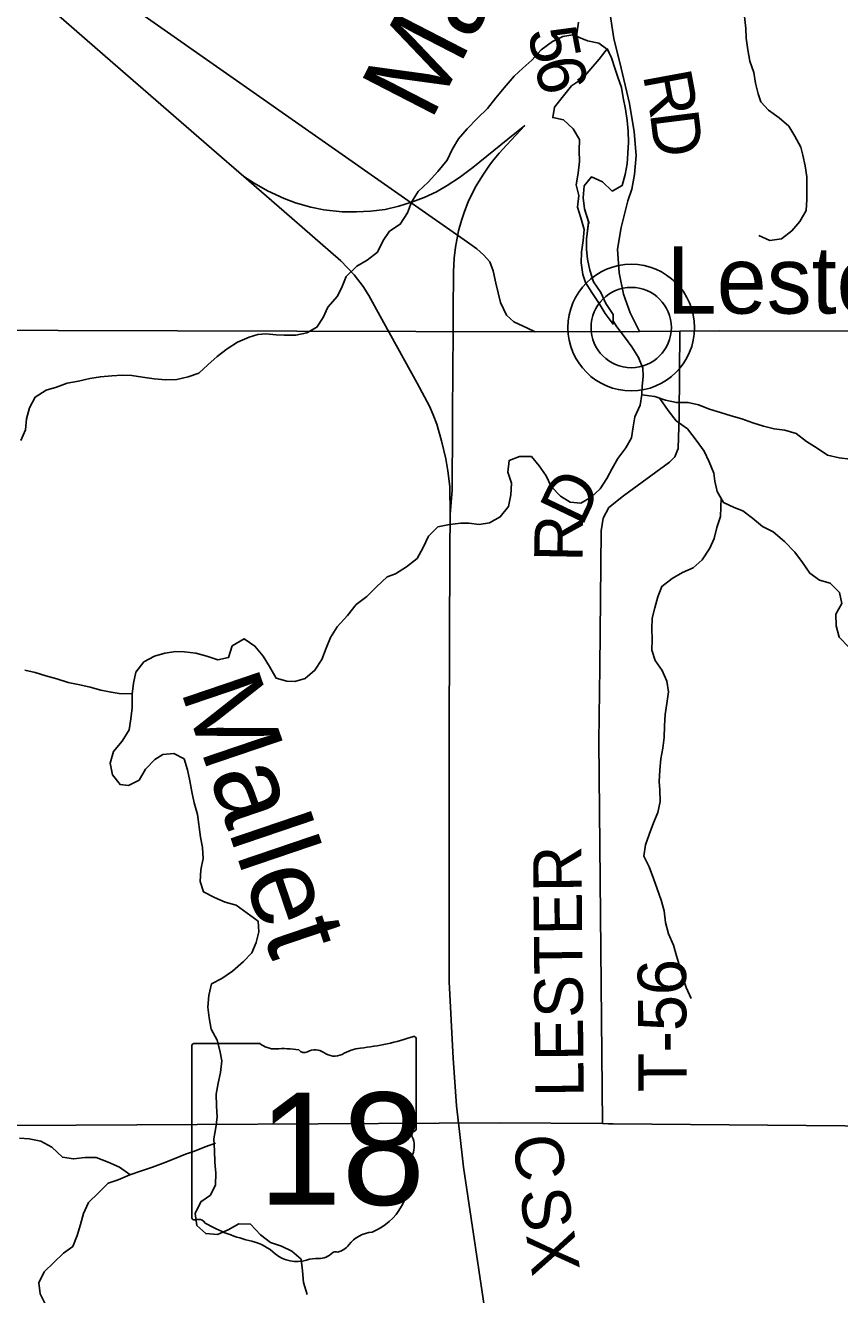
# Model space of a CAD drawing. Extents: x 1985906 to 2277390, y 930619 to 1324581.
# Drawn here: x 2119498 to 2124548, y 1153220 to 1161092 of the extents above; entities that cross this region are included whole.
import ezdxf

# ---------------------------------------------------------------- set-up
doc = ezdxf.new("R2010")
doc.units = 0
for name, color, linetype in [('GM_X_County_Road', 7, 'Continuous'), ('GM_X_County_Road_Text', 7, 'Continuous'), ('GM_X_Minor_Lake', 7, 'Continuous'), ('GM_X_Minor_River', 7, 'Continuous'), ('GM_X_Minor_River_Text', 7, 'Continuous'), ('GM_X_Rail_Line', 7, 'Continuous'), ('GM_X_Rail_Line_Text', 7, 'Continuous'), ('GM_X_State_Location', 7, 'Continuous'), ('GM_X_State_Route', 7, 'Continuous'), ('GM_X_State_Shield', 7, 'Continuous'), ('GM_X_Township_Road', 7, 'Continuous'), ('GM_X_Township_Road_Text', 7, 'Continuous'), ('GM_X_Unincorporated', 7, 'Continuous'), ('GM_X_Unincorporated_Location', 7, 'Continuous'), ('GM_X_Unincorporated_Text', 7, 'Continuous')]:
    doc.layers.add(name, color=color, linetype=linetype)

msp = doc.modelspace()

# ---------------------------------------------------------------- linework, layer by layer
at = {"layer": 'GM_X_County_Road'}
msp.add_lwpolyline([(2123307.7, 1159193.1), (2123249, 1159309.1), (2123208.2, 1159425.2), (2123181.4, 1159557.5), (2123170.4, 1159703.9), (2123193.6, 1159838.4), (2123234.5, 1160003.1), (2123260.1, 1160075.5), (2123275.5, 1160167.9), (2123286.7, 1160284.3), (2123273.8, 1160430.7), (2123244.7, 1160607), (2123193.3, 1160825.4), (2123148.1, 1161009.7), (2123121, 1161186.1)], dxfattribs=at)
at = {"layer": 'GM_X_Minor_Lake'}
for points in [[(2123106.6, 1160946.8), (2123057.6, 1160882), (2122952.7, 1160762.1), (2122886.3, 1160716.2), (2122835.8, 1160654.3), (2122779.3, 1160584.3), (2122769, 1160520.1), (2122835.1, 1160505.6), (2122895, 1160451.1), (2122934.8, 1160384.6), (2122932.5, 1160316.3), (2122934.1, 1160248), (2122927.7, 1160175.8), (2122913.4, 1160103.5), (2122931.1, 1160037.2), (2122922.7, 1159964.9), (2122942.4, 1159898.5), (2122964.1, 1159826.1), (2122957.8, 1159757.9), (2122947.4, 1159685.6), (2122945.1, 1159619.3), (2122954.7, 1159547), (2122972.5, 1159496.7), (2123012.3, 1159434.2), (2123056.1, 1159367.7), (2123093.9, 1159305.2), (2123143.7, 1159238.7), (2123144, 1159298.9), (2123098.3, 1159367.5), (2123066.5, 1159435.9), (2123022.7, 1159500.4), (2122999, 1159572.9), (2122985.3, 1159641.2), (2122977.6, 1159701.5), (2122977.9, 1159765.8), (2122990.8, 1159873.9)], [(2123106, 1160946), (2123057.6, 1160882), (2122952.7, 1160762.1), (2122886.3, 1160716.2), (2122835.8, 1160654.3), (2122779.3, 1160584.3), (2122769, 1160520.1), (2122835.1, 1160505.6), (2122895, 1160451.1), (2122934.8, 1160384.6), (2122932.5, 1160316.3), (2122934.1, 1160248), (2122927.7, 1160175.8), (2122913.4, 1160103.5), (2122931.1, 1160037.2), (2122922.7, 1159964.9), (2122942.4, 1159898.5), (2122964.1, 1159826.1), (2122957.8, 1159757.9), (2122947.4, 1159685.6), (2122945.1, 1159619.3), (2122954.7, 1159547), (2122972.5, 1159496.7), (2123012.3, 1159434.2), (2123056.1, 1159367.7), (2123093.9, 1159305.2), (2123143.7, 1159238.7), (2123144, 1159298.9), (2123098.3, 1159367.5), (2123066.5, 1159435.9), (2123022.7, 1159500.4), (2122999, 1159572.9), (2122985.3, 1159641.2), (2122977.6, 1159701.5), (2122977.9, 1159765.8), (2122990, 1159866.9)], [(2122994.1, 1159862.7), (2122966.8, 1159954.6), (2122957.1, 1160023), (2122963.5, 1160097.2), (2123009.9, 1160153.2), (2123077.9, 1160120.7), (2123137.8, 1160064.1), (2123200.1, 1160097.9), (2123218.5, 1160166.1), (2123230.9, 1160232.3), (2123235.2, 1160298.6), (2123239.5, 1160366.8), (2123235.9, 1160435.1), (2123230.2, 1160501.5), (2123220.5, 1160571.8), (2123204.8, 1160642.2), (2123195.1, 1160706.5), (2123173.4, 1160770.9), (2123155.5, 1160821.2), (2123133.8, 1160889.6), (2123106, 1160948)], [(2122990.8, 1159873.9), (2122966.8, 1159954.6), (2122957.1, 1160023), (2122963.5, 1160097.2), (2123009.9, 1160153.2), (2123077.9, 1160120.7), (2123137.8, 1160064.1), (2123200.1, 1160097.9), (2123218.5, 1160166.1), (2123230.9, 1160232.3), (2123235.2, 1160298.6), (2123239.5, 1160366.8), (2123235.9, 1160435.1), (2123230.2, 1160501.5), (2123220.5, 1160571.8), (2123204.8, 1160642.2), (2123195.1, 1160706.5), (2123173.4, 1160770.9), (2123155.5, 1160821.2), (2123133.8, 1160889.6), (2123106.6, 1160946.8)]]:
    msp.add_lwpolyline(points, dxfattribs=at)
at = {"layer": 'GM_X_Minor_River'}
for points in [[(2122916.9, 1161025.4), (2122928.3, 1161111.6)], [(2124046.9, 1159788), (2124115, 1159757.5), (2124187.2, 1159767.2), (2124251.7, 1159817), (2124302.1, 1159875), (2124340.5, 1159943.1), (2124344.9, 1160011.3), (2124345.6, 1160151.9), (2124333.9, 1160220.2), (2124320.2, 1160286.6), (2124308.4, 1160336.9), (2124270.6, 1160405.4), (2124232.8, 1160465.8), (2124172.9, 1160518.4), (2124106.9, 1160566.9), (2124059.1, 1160617.4), (2124043.3, 1160667.7), (2124027.5, 1160734.1), (2124015.8, 1160800.4), (2123992.1, 1160870.8), (2123978.4, 1160939.2), (2123968.7, 1161011.5), (2123967, 1161071.8), (2123957.4, 1161146.2)], [(2119470, 1158517.9), (2119498.4, 1158584), (2119504.8, 1158652.2), (2119523.2, 1158720.4), (2119559.6, 1158786.5), (2119628, 1158830.3), (2119692.3, 1158848), (2119756.6, 1158871.8), (2119828.8, 1158885.4), (2119899.1, 1158901.1), (2119963.3, 1158912.8), (2120033.6, 1158918.4), (2120097.7, 1158922.1), (2120157.9, 1158919.8), (2120224, 1158909.3), (2120296.2, 1158898.9), (2120370.4, 1158892.5), (2120438.6, 1158896.1), (2120508.8, 1158911.8), (2120573.1, 1158935.5), (2120629.5, 1158987.4), (2120687.9, 1159037.3), (2120750.4, 1159085.2), (2120814.7, 1159127), (2120887.1, 1159158.7), (2120939.3, 1159174.5), (2120989.5, 1159178.2), (2121053.6, 1159171.9), (2121103.8, 1159169.6), (2121176, 1159171.2), (2121244.2, 1159184.9), (2121306.6, 1159220.7), (2121345, 1159280.7), (2121373.4, 1159344.8), (2121433.9, 1159412.8), (2121462.2, 1159472.9), (2121488.6, 1159535), (2121553.1, 1159598.9), (2121617.5, 1159634.7), (2121681.9, 1159684.6), (2121718.3, 1159756.7), (2121756.7, 1159814.7), (2121823.1, 1159858.5), (2121867.6, 1159928.6), (2121894, 1159994.7), (2121934.4, 1160060.7), (2121996.9, 1160118.6), (2122055.4, 1160184.6), (2122113.9, 1160256.6), (2122146.3, 1160322.7), (2122184.7, 1160388.7), (2122239.2, 1160450.7), (2122301.7, 1160516.6), (2122364.2, 1160576.5), (2122416.6, 1160642.5), (2122467.1, 1160704.5), (2122529.6, 1160776.4), (2122584, 1160826.3), (2122640.4, 1160876.2), (2122696.9, 1160940.2), (2122767.3, 1160992), (2122831.6, 1161021.8), (2122893.9, 1161033.5)], [(2123103.2, 1160945.8), (2123054.1, 1160982.4), (2122983.9, 1160994.9), (2122893.8, 1161033.8)], [(2120160.2, 1156943.5), (2120168.6, 1157011.7), (2120182.9, 1157079.9), (2120233.4, 1157143.9), (2120299.7, 1157179.7), (2120364, 1157197.4), (2120432.3, 1157209.1), (2120484.4, 1157206.8), (2120556.5, 1157198.4), (2120624.6, 1157179.9), (2120692.7, 1157157.4), (2120759, 1157171.1), (2120781.4, 1157243.3), (2120855.8, 1157287.1), (2120921.8, 1157242.5), (2120973.6, 1157180), (2121011.4, 1157115.5), (2121053.2, 1157043), (2121119.3, 1157024.5), (2121169.4, 1157022.2), (2121233.7, 1157042), (2121294.1, 1157091.8), (2121336.5, 1157157.9), (2121362.9, 1157230.1), (2121391.3, 1157296.2), (2121431.8, 1157362.2), (2121496.3, 1157432.2), (2121550.8, 1157500.2), (2121615.2, 1157550), (2121675.7, 1157609.9), (2121742.2, 1157671.8), (2121794.4, 1157689.6), (2121862.8, 1157733.4), (2121927.2, 1157785.3), (2121965.7, 1157853.3), (2121998.1, 1157923.5), (2122056.6, 1157981.4), (2122128.8, 1157997.1), (2122199.1, 1158004.7), (2122249.2, 1158004.4), (2122313.3, 1157996), (2122377.6, 1158005.7), (2122443.9, 1158043.5), (2122494.4, 1158107.5), (2122508.8, 1158179.7), (2122513.2, 1158252), (2122491.4, 1158320.4), (2122497.8, 1158392.7), (2122562.1, 1158418.4), (2122636.3, 1158418), (2122684.2, 1158359.5), (2122728, 1158299), (2122759.7, 1158232.6), (2122817.6, 1158172), (2122877.6, 1158135.5), (2122943.7, 1158129.1), (2123008.1, 1158164.9), (2123062.5, 1158216.8), (2123104.9, 1158280.9), (2123137.3, 1158343), (2123173.7, 1158405), (2123222.2, 1158471), (2123256.6, 1158533.1), (2123267, 1158601.3), (2123277.3, 1158663.5), (2123311.8, 1158735.6), (2123322.1, 1158801.9), (2123324.4, 1158852.1), (2123330.7, 1158916.3), (2123326.9, 1158966.5), (2123301.2, 1159030.9), (2123259.4, 1159097.5), (2123213.6, 1159160), (2123165.7, 1159222.5), (2123141.6, 1159261.5)], [(2123321.1, 1158800.2), (2123402.3, 1158789.4), (2123468.3, 1158766.9), (2123536.4, 1158752.5), (2123608.7, 1158752.1), (2123672.8, 1158737.7), (2123740.8, 1158711.2), (2123808.9, 1158690.7), (2123875, 1158670.3), (2123941.1, 1158651.8), (2124009.2, 1158627.4), (2124075.2, 1158606.9), (2124141.3, 1158588.5), (2124209.5, 1158582.1), (2124279.6, 1158559.6), (2124343.5, 1158511.1), (2124409.5, 1158470.5), (2124473.5, 1158426), (2124545.6, 1158409.5), (2124613.7, 1158401.1)], [(2123433.6, 1158778.2), (2123484.1, 1158702.6), (2123533.9, 1158640), (2123605.8, 1158589.4), (2123657.6, 1158518.8), (2123707.4, 1158450.3), (2123739.2, 1158385.8), (2123769, 1158315.4), (2123774.7, 1158265.1), (2123788.4, 1158200.8), (2123828.2, 1158132.3), (2123894.3, 1158101.8), (2123948.3, 1158081.4), (2124008.2, 1158034.9), (2124070.2, 1157984.3), (2124136.2, 1157949.8), (2124206.1, 1157891.2), (2124269.9, 1157824.6), (2124317.7, 1157760), (2124363.5, 1157693.5), (2124423.5, 1157651), (2124489.6, 1157632.6), (2124547.5, 1157574), (2124561.2, 1157505.6), (2124524.8, 1157439.6), (2124526.4, 1157367.2), (2124546.1, 1157296.8), (2124606, 1157236.2)], [(2123628.5, 1155056.3), (2123596.8, 1155124.8), (2123573, 1155193.2), (2123555.3, 1155259.6), (2123537.6, 1155322), (2123517.9, 1155386.4), (2123486.1, 1155456.8), (2123468.4, 1155527.2), (2123460.7, 1155599.6), (2123441, 1155666), (2123417.3, 1155736.4), (2123393.5, 1155800.8), (2123367.8, 1155873.3), (2123334.1, 1155939.7), (2123344.4, 1156010), (2123366.8, 1156074.1), (2123393.2, 1156146.3), (2123421.6, 1156210.4), (2123436, 1156278.6), (2123432.4, 1156350.9), (2123428.6, 1156401.2), (2123433, 1156473.5), (2123439.3, 1156543.7), (2123451.7, 1156609.9), (2123460, 1156674.2), (2123462.4, 1156746.5), (2123466.8, 1156818.7), (2123477.1, 1156887), (2123487.5, 1156959.2), (2123475.8, 1157023.6), (2123448, 1157090), (2123404.2, 1157152.5), (2123384.5, 1157216.9), (2123384.8, 1157283.1), (2123383.1, 1157349.4), (2123385.5, 1157415.7), (2123401.8, 1157479.9), (2123420.2, 1157548.1), (2123446.6, 1157612.2), (2123509, 1157662.1), (2123573.4, 1157697.9), (2123639.7, 1157727.6), (2123696.1, 1157777.5), (2123742.6, 1157849.6), (2123771, 1157909.7), (2123787.4, 1157977.9), (2123809.7, 1158046), (2123814.5, 1158161.7)], [(2119495.1, 1157091.8), (2119559.2, 1157077.4), (2119625.3, 1157056.9), (2119693.4, 1157038.5), (2119763.5, 1157016), (2119835.6, 1157001.5), (2119899.7, 1156987.1), (2119965.8, 1156968.7), (2120029.9, 1156956.2), (2120080, 1156947.9), (2120160.5, 1156944.9)], [(2121246.7, 1153220), (2121223.2, 1153294.1), (2121217.5, 1153366.4), (2121209.8, 1153438.8), (2121151.9, 1153489.3), (2121085.9, 1153519.8), (2121017.8, 1153542.3), (2120955.9, 1153590.8), (2120894, 1153657.5), (2120821.8, 1153657.9), (2120755.5, 1153622.1), (2120689.2, 1153592.3), (2120617, 1153598.7), (2120561.1, 1153649.3), (2120551.4, 1153723.6), (2120585.9, 1153795.8), (2120646.2, 1153837.6), (2120676.6, 1153901.7), (2120679, 1153974), (2120673.3, 1154042.3), (2120671.7, 1154114.6), (2120668, 1154185), (2120680.4, 1154257.2), (2120688.7, 1154321.4), (2120683.1, 1154389.8), (2120681.4, 1154462.1), (2120693.8, 1154530.3), (2120708.2, 1154596.5), (2120716.5, 1154668.8), (2120704.8, 1154733.1), (2120687.1, 1154797.5), (2120651.3, 1154866), (2120637.6, 1154936.3), (2120629.9, 1155002.7), (2120636.3, 1155074.9), (2120652.7, 1155147.2), (2120717.1, 1155180.9), (2120783.5, 1155226.8), (2120852, 1155286.6), (2120902.4, 1155340.6), (2120928.8, 1155404.7), (2120947.1, 1155468.9), (2120941.4, 1155535.2), (2120873.5, 1155585.8), (2120805.5, 1155634.4), (2120737.5, 1155654.8), (2120671.4, 1155683.3), (2120603.4, 1155717.9), (2120581.6, 1155782.2), (2120586, 1155854.5), (2120600.4, 1155924.8), (2120596.7, 1155993.1), (2120585, 1156057.4), (2120565.7, 1156198.1), (2120546, 1156270.5), (2120530.2, 1156338.9), (2120518.6, 1156407.2), (2120502.9, 1156475.6), (2120483.1, 1156542), (2120419.1, 1156576.5), (2120350.9, 1156568.8), (2120300.6, 1156539), (2120244.1, 1156479.1), (2120203.7, 1156411), (2120137.4, 1156377.2), (2120085.2, 1156383.5), (2120039.4, 1156444), (2120023.7, 1156516.4), (2120044.1, 1156588.6), (2120098.6, 1156652.6), (2120141.1, 1156722.6), (2120151.4, 1156790.9), (2120159.8, 1156859.1), (2120160.5, 1156948.1)], [(2120145.6, 1153964.2), (2120081.2, 1154010.2), (2120010.8, 1154042.1), (2119936.5, 1154069.9), (2119868.2, 1154069.7), (2119796, 1154061.4), (2119727.8, 1154073.3), (2119663.3, 1154133.3), (2119594.9, 1154171.2), (2119522.6, 1154185.1), (2119462.4, 1154190.9)], [(2120676.5, 1154158.7), (2120614.4, 1154136.4), (2120546.3, 1154110.1), (2120492.2, 1154091.9), (2120422.1, 1154061.5), (2120352, 1154035.2), (2120285.9, 1154010.8), (2120217.7, 1153988.5), (2120145.6, 1153962.2), (2120073.5, 1153931.8), (2120011.4, 1153911.5), (2119951.5, 1153851.1), (2119889.6, 1153790.6), (2119859.8, 1153722.3), (2119840, 1153653.9), (2119820.3, 1153585.6), (2119792.5, 1153517.2), (2119734.5, 1153476.9), (2119674.5, 1153418.4), (2119614.6, 1153362), (2119580.8, 1153293.6), (2119589.1, 1153225.3), (2119623.6, 1153159.2)]]:
    msp.add_lwpolyline(points, dxfattribs=at)
at = {"layer": 'GM_X_Rail_Line'}
for points in [[(2120852.4, 1160155.2), (2120652.8, 1160328.9), (2120040.3, 1160858.9), (2118456.4, 1162237.5), (2117861.3, 1162751.1), (2117709.9, 1162885), (2117618.1, 1162962.9), (2117550.7, 1163018), (2117466.7, 1163086.3), (2117333.4, 1163187.9), (2116922.4, 1163474.1), (2115790.2, 1164266.3), (2114248.1, 1165366.5), (2113730.7, 1165737.4), (2113477.7, 1165918.3), (2113358.5, 1166014.7)], [(2122596.3, 1160470.4), (2122491, 1160386), (2122272.9, 1160209.4), (2122191.1, 1160148.1), (2122115.2, 1160099.7), (2122047.2, 1160060), (2121970.9, 1160023.4), (2121893.9, 1159995.1), (2121814.5, 1159970.5), (2121730, 1159950.3), (2121638, 1159939.6), (2121552.2, 1159934.5), (2121464, 1159935.8), (2121349.2, 1159948.4), (2121267.9, 1159964.8), (2121173.9, 1159990.6), (2121103.3, 1160017.1), (2120999.3, 1160066.3), (2120916.7, 1160112.3), (2120852.4, 1160155.2)], [(2122153.5, 1159563.5), (2122157.6, 1159647.3), (2122165.4, 1159715.2), (2122185.4, 1159817.5), (2122203.2, 1159882), (2122222.4, 1159938.4), (2122245.1, 1159996.6), (2122269.5, 1160048.5), (2122294, 1160095.6), (2122320.7, 1160140.8), (2122342.9, 1160175.7), (2122373, 1160219.1), (2122395.6, 1160249.1), (2122437.5, 1160299.5), (2122483.8, 1160351.8), (2122596.3, 1160470.4)], [(2121453.9, 1159630.6), (2121104, 1159937.1), (2120852.4, 1160155.2)], [(2122133.3, 1158061), (2122131, 1158231), (2122119, 1158328.1), (2122105.8, 1158403.7), (2122079.9, 1158514.7), (2122049.7, 1158617.5), (2122028.2, 1158675.5), (2122004.9, 1158729.7), (2121928.6, 1158872.8), (2121720.6, 1159247.3), (2121663.8, 1159353.2), (2121628.5, 1159415.7), (2121592.6, 1159471.8), (2121537.7, 1159545.5), (2121453.9, 1159630.6)], [(2122148.6, 1159024), (2122151.3, 1159113.8), (2122152, 1159315.1), (2122153.5, 1159563.5)], [(2122133.3, 1158061), (2122144.6, 1158208), (2122148.3, 1158609.9), (2122148.6, 1159024)], [(2122972.5, 1148922.9), (2122941.7, 1149160.3), (2122860.1, 1149696.5), (2122733.9, 1150551.1), (2122671.5, 1150972.1), (2122553.6, 1151760.8), (2122433, 1152555.9), (2122215, 1154010.6), (2122190.7, 1154231.8), (2122172.4, 1154391.6), (2122150.9, 1154687.2), (2122127.2, 1155158.8), (2122126.7, 1156720), (2122131, 1157826.3), (2122133.3, 1158061)]]:
    msp.add_lwpolyline(points, dxfattribs=at)
at = {"layer": 'GM_X_State_Route'}
for points in [[(2121850.5, 1160020.3), (2117515.4, 1163056.1)], [(2122612.1, 1159213), (2122526.8, 1159252.2), (2122482.4, 1159294.2), (2122445.8, 1159372.4), (2122416.9, 1159492.7), (2122400.4, 1159569), (2122378, 1159625.1), (2122339.6, 1159669.1), (2122299.2, 1159705), (2122240.8, 1159746.9), (2121850.5, 1160020.3)], [(2126779.5, 1159191.6), (2126346.2, 1159195.5), (2123802.8, 1159196.5), (2123557.8, 1159194.8), (2123307.7, 1159193.1), (2122660.1, 1159190.8), (2122612.1, 1159213)], [(2102815.7, 1154354.1), (2105209.8, 1154373.2), (2105284.6, 1154371.7), (2106450.5, 1154346.3), (2107267.7, 1154341.3), (2107855, 1154337.3), (2110435, 1154319.4), (2113184.2, 1154330.1), (2116530.8, 1154278.2), (2117482.8, 1154274.8), (2119323, 1154268.2), (2119439.6, 1154268.9), (2122437.9, 1154286), (2123076.9, 1154280.2), (2123115.8, 1154279.8), (2123143, 1154279.6)], [(2123143, 1154279.6), (2124820.3, 1154264.1)]]:
    msp.add_lwpolyline(points, dxfattribs=at)
at = {"layer": 'GM_X_State_Shield'}
for p, q in [((2120530.3, 1154758.9), (2120530.3, 1153702.3)), ((2120951.8, 1154777.1), (2120544, 1154777.1)), ((2121922.5, 1154250.5), (2121922.5, 1154803.3)), ((2121922.4, 1154250.7), (2121922.5, 1154250.5))]:
    msp.add_line(p, q, dxfattribs=at)
for centre, radius, start, end in [((2121426.6, 1156217.6), 1476.4, 275.84447, 288.90645), ((2121907.1, 1154805.5), 15.5, 351.86209, 97.738), ((2120546.3, 1154761.1), 16.1, 98.1301, 188.1301), ((2121048.8, 1154899.7), 156.4, 231.61951, 271.11188), ((2121100.7, 1154183.9), 561.6, 80.48669, 94.98827), ((2121228.2, 1154766.6), 45.1, 219.79206, 297.10237), ((2121294.5, 1154644.5), 93.8, 54.46668, 119.14113), ((2121614.9, 1154454.3), 297, 97.34618, 120.76885), ((2121415.6, 1154812), 112.9, 233.85621, 294.82819), ((2121918.9, 1154209.9), 24, 107.94398, 210.33697), ((2121766.3, 1154140.1), 144, 340.03296, 23.64957), ((2121906, 1154248.4), 16.6, 289.60381, 7.73413), ((2121978, 1154019.2), 104.8, 136.8065, 186.92959), ((2121509.3, 1153948.9), 369.3, 292.30889, 8.98584), ((2120546.4, 1153699.9), 16.3, 171.95839, 258.30661), ((2120548.9, 1153808), 124.2, 267.33899, 280.60386), ((2120574.3, 1153641.3), 44.8, 29.74838, 93.27175), ((2121139.6, 1154590.6), 1066.1, 240.41292, 257.1985), ((2121665, 1153405.6), 202.2, 94.40312, 142.57675), ((2120821.7, 1153227.6), 333.6, 47.18416, 75.83597), ((2121320.3, 1153556.9), 112.8, 268.77702, 315.54927), ((2121422.3, 1153454.6), 31.8, 65.75173, 132.64842), ((2121408.8, 1153599.8), 119.3, 282.87319, 323.27711), ((2121182.5, 1153636.1), 211.7, 230.70037, 286.29184), ((2121304.8, 1153270.7), 173.9, 85.69512, 111.20995)]:
    msp.add_arc(centre, radius, start, end, dxfattribs=at)
at = {"layer": 'GM_X_Township_Road'}
for points in [[(2117481.5, 1159205.4), (2122660.1, 1159190.8)], [(2123076.9, 1154280.2), (2123055.8, 1156651.9), (2123060.9, 1157111.3), (2123069.5, 1157956), (2123081, 1158036.3), (2123116.6, 1158100.7), (2123208.2, 1158173.4), (2123492.9, 1158383.6), (2123526.8, 1158415.9), (2123546.4, 1158468.1), (2123553.1, 1158668.8), (2123557.8, 1159194.8)]]:
    msp.add_lwpolyline(points, dxfattribs=at)
at = {"layer": 'GM_X_Unincorporated'}
for radius in [392.8, 249]:
    msp.add_circle((2123255.9, 1159217.7), radius, dxfattribs=at)
at = {"layer": 'GM_X_Unincorporated_Location'}
msp.add_line((2123255.9, 1159217.7), (2123255.9, 1159217.7), dxfattribs=at)

# ---------------------------------------------------------------- texts
at = {"layer": 'GM_X_County_Road_Text'}
for s, rotation, p in [('5', 280.9017, (2122613.3, 1161056.9)), ('6', 283.53965, (2122651.4, 1160860.7)), ('R', 280.45183, (2123327.2, 1160785.2)), ('D', 277.1806, (2123371.2, 1160547.3))]:
    msp.add_text(s, height=300, rotation=rotation, dxfattribs=at).set_placement(p)
at = {"layer": 'GM_X_Minor_River_Text'}
for height, rotation, p in [(500.17, 62.75526, (2122010.9, 1160489.2)), (500.23, 288.75759, (2120457.8, 1156972))]:
    msp.add_text('Mallet', height=height, rotation=rotation, dxfattribs=at).set_placement(p)
at = {"layer": 'GM_X_Rail_Line_Text'}
for s, rotation, p in [('C', 277.08289, (2122520.6, 1154195.5)), ('S', 278.58429, (2122562.3, 1153861.1)), ('X', 278.75861, (2122603.2, 1153590))]:
    msp.add_text(s, height=299, rotation=rotation, dxfattribs=at).set_placement(p)
at = {"layer": 'GM_X_State_Location'}
for s in ['s', 'r']:
    msp.add_text(s, height=1, dxfattribs=at).set_placement((2121210.7, 1154160.3))
msp.add_text('18', height=1, rotation=0.00001, dxfattribs=at).set_placement((2120958.9, 1154087.6))
at = {"layer": 'GM_X_State_Shield'}
msp.add_text('18', height=696.1, dxfattribs=at).set_placement((2120942.6, 1153776.8))
at = {"layer": 'GM_X_Township_Road_Text'}
for s, rotation, p in [('D', 64.39616, (2122949.9, 1157976.5)), ('R', 88.89926, (2122952.9, 1157762.9)), ('LESTER', 90.56141, (2122961.7, 1154445.7)), ('T-56', 90.35349, (2123600.4, 1154476.5))]:
    msp.add_text(s, height=300, rotation=rotation, dxfattribs=at).set_placement(p)
at = {"layer": 'GM_X_Unincorporated_Text'}
msp.add_text('Lester', height=417, rotation=0.00001, dxfattribs=at).set_placement((2123475.7, 1159304.2))

doc.saveas('drawing.dxf')
